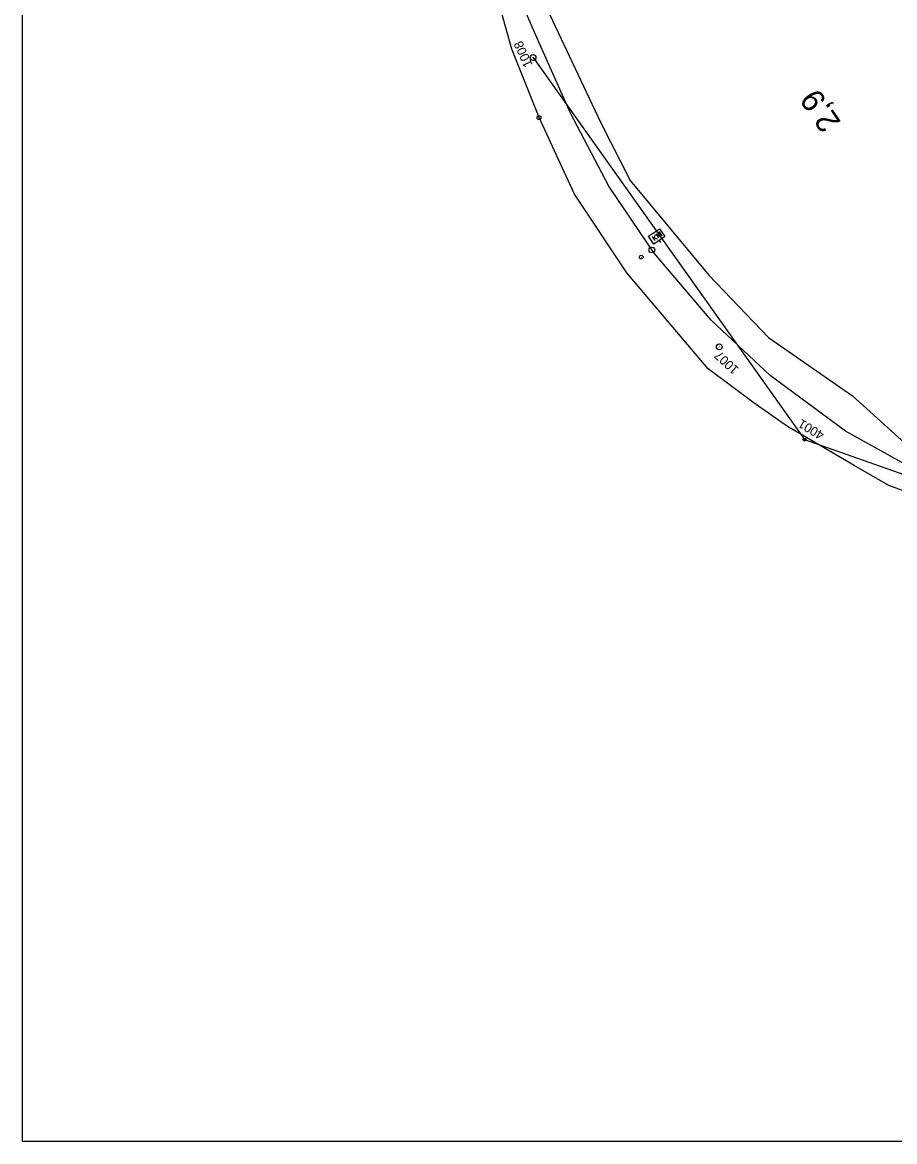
# Model space of a CAD drawing. Extents: x -728800 to -728100, y -1073200 to -1072700.
# Drawn here: x -728800 to -728571.1, y -1073200 to -1072906.2 of the extents above; entities that cross this region are included whole.
import ezdxf

# ---------------------------------------------------------------- set-up
doc = ezdxf.new("R2010")
doc.units = 0
for name, color, linetype in [('A1_OBVOD Spravy železnic', 7, 'Continuous'), ('B4_Bodové pole', 7, 'Continuous'), ('B6_JŽM', 7, 'Continuous')]:
    doc.layers.add(name, color=color, linetype=linetype)

msp = doc.modelspace()

# ---------------------------------------------------------------- linework, layer by layer
at = {"layer": 'A1_OBVOD Spravy železnic'}
for points in [[(-728664.64, -1072897.67), (-728648.31, -1072932.44), (-728640.48, -1072947.72), (-728619.81, -1072972.56), (-728604.14, -1072988.92), (-728582.13, -1073004.22), (-728564.68, -1073020.02)], [(-728541.12, -1073039.22), (-728572.55, -1073027.78), (-728581.66, -1073022.5), (-728594.83, -1073014.86), (-728598.74, -1073012.6), (-728600.31, -1073011.5), (-728608.33, -1073005.87), (-728620.02, -1072997.18), (-728641.33, -1072971.93), (-728655.13, -1072951.34), (-728658.89, -1072943.19), (-728664.41, -1072931.23), (-728671.52, -1072913.23), (-728674.84, -1072901.32)]]:
    msp.add_lwpolyline(points, dxfattribs=at)
at = {"layer": 'B4_Bodové pole'}
for p, q in [((-728665.94, -1072915.49), (-728665.98, -1072915.4)), ((-728665.94, -1072915.49), (-728665.98, -1072915.4)), ((-728617.07, -1072991.42), (-728617.15, -1072991.35)), ((-728594.73, -1073015.73), (-728594.68, -1073015.74)), ((-728594.71, -1073015.73), (-728594.71, -1073015.73))]:
    msp.add_line(p, q, dxfattribs=at)
msp.add_lwpolyline([(-728665.96, -1072915.44), (-728594.71, -1073015.73), (-728502.09, -1073048.37), (-728347.46, -1073023.54)], dxfattribs=at)
for centre, radius in [((-728665.96, -1072915.44), 0.756), ((-728665.96, -1072915.44), 0.756), ((-728617.11, -1072991.39), 0.756), ((-728594.71, -1073015.73), 0.378)]:
    msp.add_circle(centre, radius, dxfattribs=at)
at = {"layer": 'B6_JŽM'}
for p, q in [((-728664.46, -1072931.23), (-728664.36, -1072931.23)), ((-728634.69, -1072962.47), (-728634, -1072963.51)), ((-728634, -1072962.01), (-728634.23, -1072963.16)), ((-728634.14, -1072962.74), (-728633.3, -1072963.04)), ((-728632.46, -1072963.97), (-728632.81, -1072963.45)), ((-728637.54, -1072967.9), (-728637.59, -1072967.82))]:
    msp.add_line(p, q, dxfattribs=at)
for points in [[(-728800, -1073200), (-728800, -1072700), (-728100, -1072700), (-728100, -1073200), (-728800, -1073200)], [(-728300.81, -1073024.35), (-728320.8, -1073026.91), (-728374.01, -1073033.72), (-728429.1, -1073040.75), (-728461.93, -1073044.27), (-728481.2, -1073044.81), (-728499.35, -1073043.65), (-728506.01, -1073042.74), (-728514.57, -1073041.33), (-728535.85, -1073036), (-728561.35, -1073026.11), (-728583.96, -1073013.52), (-728603.76, -1072998.89), (-728619.19, -1072984.42), (-728634.19, -1072966.82), (-728646.08, -1072949.19), (-728656.18, -1072930.07), (-728664.99, -1072910.23), (-728668.63, -1072901.81), (-728681.25, -1072876.02), (-728691.89, -1072859.66)], [(-728632.96, -1072962.81), (-728633.66, -1072961.77), (-728632.56, -1072962.54), (-728632.87, -1072961.24), (-728632.17, -1072962.28)]]:
    msp.add_lwpolyline(points, dxfattribs=at)
msp.add_lwpolyline([(-728634.25, -1072964.42), (-728635.64, -1072962.37), (-728632.75, -1072960.42), (-728631.36, -1072962.47)], close=True, dxfattribs=at)
for centre, radius in [((-728664.41, -1072931.23), 0.499), ((-728637.57, -1072967.86), 0.5), ((-728634.77, -1072965.97), 0.75)]:
    msp.add_circle(centre, radius, dxfattribs=at)

# ---------------------------------------------------------------- texts
at = {"layer": 'B4_Bodové pole'}
for s, rotation, p in [('1008', 113.9263, (-728666.03, -1072917.38)), ('1008', 113.9263, (-728666.03, -1072917.38)), ('1007', 136.8293, (-728611.77, -1072997.12)), ('4001', 149.5614, (-728589.33, -1073013.88))]:
    msp.add_text(s, height=2.4, rotation=rotation, dxfattribs=at).set_placement(p)
at = {"layer": 'B6_JŽM'}
msp.add_text('2,9', height=6, rotation=123.9838, dxfattribs=at).set_placement((-728585.02, -1072932.44))

doc.saveas('drawing.dxf')
